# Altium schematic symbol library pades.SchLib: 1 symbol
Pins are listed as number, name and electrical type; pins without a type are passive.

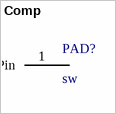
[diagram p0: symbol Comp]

## Comp
designator PAD?, comment sw
footprint PCBComponent_1
pins: 1 Pin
